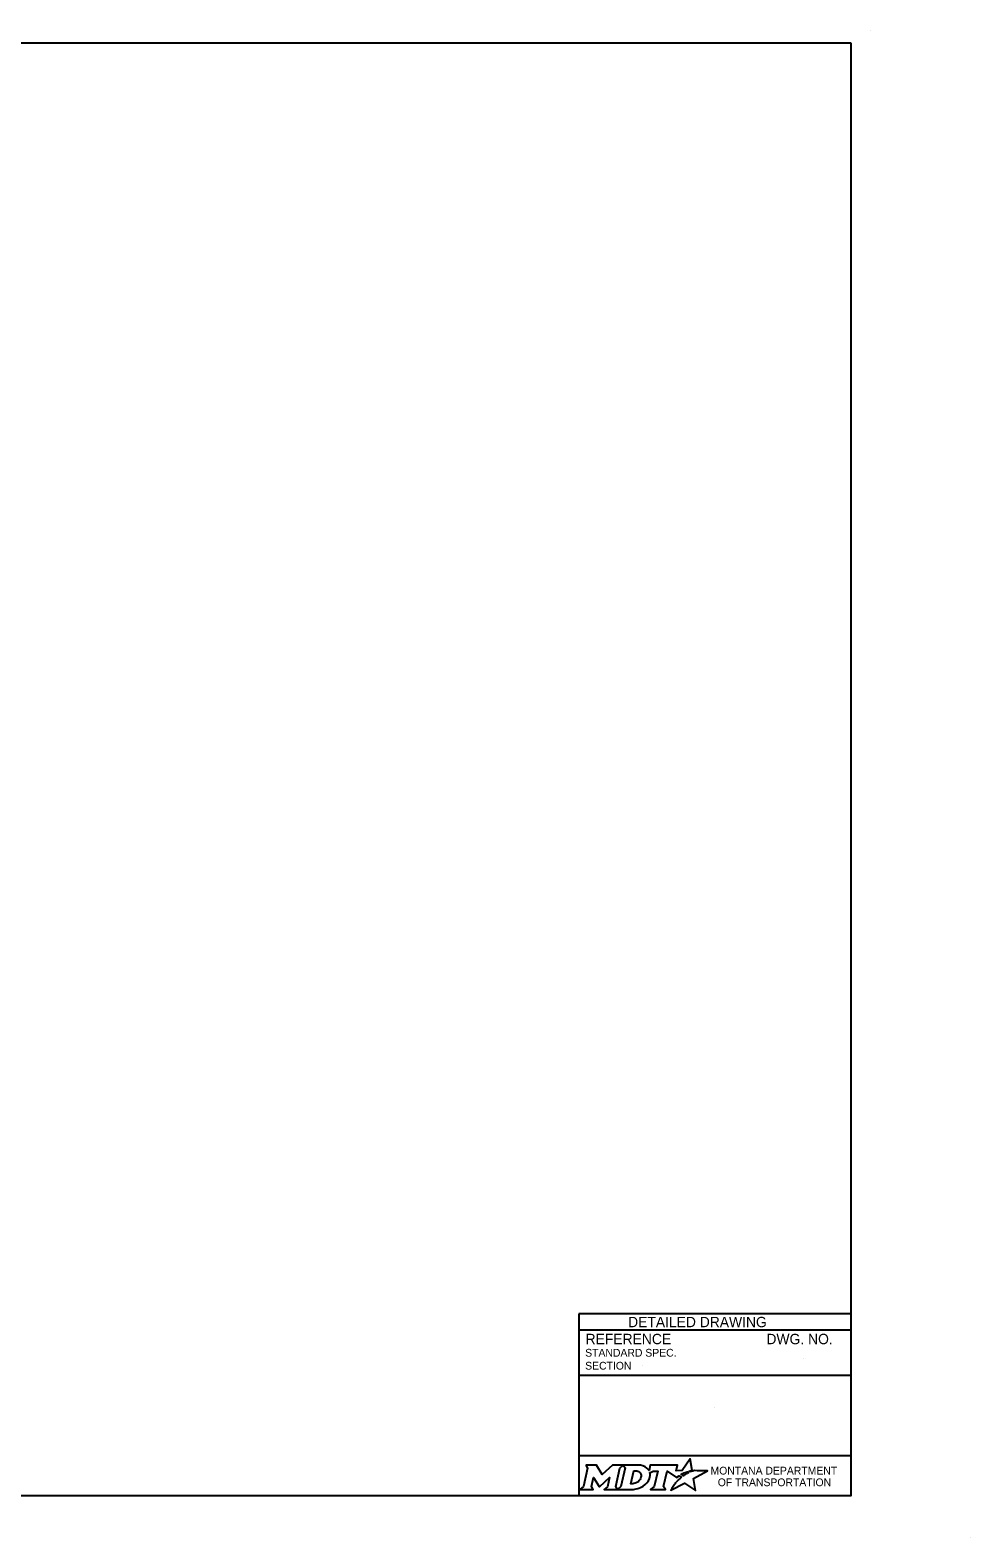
# Model space of a CAD drawing. Extents: x 49991.4 to 50021, y 49987.6 to 50011.4.
# Drawn here: x 50002.29 to 50009.54, y 49999.74 to 50011.36 of the extents above; entities that cross this region are included whole.
import ezdxf

# ---------------------------------------------------------------- set-up
doc = ezdxf.new("R2010")
doc.units = 0
doc.layers.add('Level 1', color=7, linetype='Continuous')
doc.layers.add('Level 2', color=7, linetype='Continuous')

msp = doc.modelspace()

# ---------------------------------------------------------------- linework, layer by layer
at = {"layer": 'Level 1'}
for p, q in [((50008.765, 50011.363), (50008.765, 50011.363)), ((50009.537, 49999.736), (50009.537, 49999.736))]:
    msp.add_line(p, q, dxfattribs=at)
msp.add_lwpolyline([(50008.615, 50011.263), (50000.336, 50011.263), (50000.336, 50000.062), (50008.615, 50000.062)], close=True, dxfattribs=at)
at = {"layer": 'Level 2'}
for p, q in [((50008.615, 50001.462), (50006.515, 50001.462)), ((50006.515, 50001.462), (50006.515, 50000.062)), ((50008.615, 50001.337), (50006.515, 50001.337)), ((50007.009, 50001.063), (50007.009, 50001.063)), ((50008.251, 50001.122), (50008.251, 50001.122)), ((50008.615, 50000.987), (50006.515, 50000.987)), ((50007.565, 50000.738), (50007.565, 50000.738)), ((50008.615, 50000.369), (50006.515, 50000.369))]:
    msp.add_line(p, q, dxfattribs=at)
for points in [[(50007.377, 50000.245), (50007.367, 50000.25), (50007.378, 50000.253), (50007.39, 50000.255), (50007.373, 50000.345), (50007.313, 50000.254), (50007.266, 50000.253), (50007.276, 50000.297), (50007.067, 50000.297), (50007.057, 50000.255), (50007.051, 50000.263)], [(50006.57, 50000.297), (50006.584, 50000.274), (50006.551, 50000.131), (50006.525, 50000.108), (50006.627, 50000.108), (50006.613, 50000.131), (50006.629, 50000.201), (50006.673, 50000.132), (50006.678, 50000.132), (50006.753, 50000.202), (50006.737, 50000.13), (50006.712, 50000.108), (50006.814, 50000.108), (50006.8, 50000.132), (50006.833, 50000.274)], [(50006.833, 50000.274), (50006.859, 50000.297), (50006.776, 50000.297), (50006.697, 50000.224), (50006.652, 50000.297), (50006.57, 50000.297)], [(50006.972, 50000.297), (50006.859, 50000.297), (50006.873, 50000.275), (50006.839, 50000.131), (50006.814, 50000.108), (50006.925, 50000.108)], [(50006.996, 50000.211), (50006.995, 50000.203), (50006.992, 50000.193), (50006.988, 50000.185), (50006.982, 50000.178), (50006.976, 50000.171), (50006.968, 50000.164), (50006.959, 50000.16), (50006.95, 50000.156), (50006.941, 50000.154), (50006.932, 50000.153), (50006.916, 50000.153), (50006.94, 50000.253), (50006.956, 50000.253), (50006.963, 50000.252), (50006.971, 50000.25), (50006.977, 50000.247), (50006.983, 50000.243), (50006.988, 50000.238), (50006.992, 50000.232), (50006.995, 50000.226), (50006.996, 50000.218), (50006.996, 50000.215), (50006.996, 50000.211)], [(50007.064, 50000.238), (50007.088, 50000.251), (50007.125, 50000.251), (50007.097, 50000.131), (50007.069, 50000.108), (50007.185, 50000.108), (50007.168, 50000.131), (50007.196, 50000.251), (50007.268, 50000.2), (50007.289, 50000.215), (50007.309, 50000.204)], [(50007.253, 50000.148), (50007.237, 50000.124), (50007.233, 50000.116), (50007.227, 50000.107), (50007.225, 50000.103), (50007.33, 50000.156), (50007.414, 50000.101), (50007.401, 50000.194), (50007.508, 50000.252), (50007.458, 50000.253), (50007.428, 50000.253), (50007.407, 50000.254), (50007.401, 50000.252), (50007.396, 50000.251), (50007.387, 50000.249), (50007.377, 50000.245)], [(50007.327, 50000.217), (50007.324, 50000.215), (50007.306, 50000.225), (50007.316, 50000.231), (50007.32, 50000.233), (50007.329, 50000.237), (50007.335, 50000.239), (50007.343, 50000.243), (50007.35, 50000.245), (50007.362, 50000.238), (50007.358, 50000.236), (50007.353, 50000.233), (50007.349, 50000.231), (50007.344, 50000.228), (50007.342, 50000.227), (50007.339, 50000.225), (50007.337, 50000.224), (50007.334, 50000.222), (50007.332, 50000.221), (50007.329, 50000.219), (50007.327, 50000.217)], [(50006.97, 50000.116), (50006.979, 50000.118), (50006.992, 50000.124), (50007.012, 50000.135)], [(50007.267, 50000.164), (50007.267, 50000.164)]]:
    msp.add_lwpolyline(points, dxfattribs=at)
for centre, radius, start, end in [((50006.995, 50000.219), 0.0709, 339.5329, 15.8582), ((50006.951, 50000.236), 0.118, 300.9103, 339.1383)]:
    msp.add_arc(centre, radius, start, end, dxfattribs=at)
for centre, major_axis, ratio, start_param, end_param in [((50006.97, 50000.25), (0.0834, -0.0037), 0.568097, 0.61298, 1.570796), ((50007.026, 50000.257), (0.0361, -0.0295), 0.469099, 1.225588, 1.570796), ((50006.925, 50000.257), (0, 0.148), 0.987302, 3.139398, 3.456847), ((50007.26, 50000.156), (-0.00694, -0.00806), 0.008222, 0, 3.137361), ((50007.276, 50000.174), (-0.0098, -0.0102), 0.016458, 3.141593, 6.279097), ((50007.297, 50000.194), (-0.0112, -0.0097), 0.021651, 3.157348, 6.283185)]:
    msp.add_ellipse(centre, major_axis=major_axis, ratio=ratio, start_param=start_param, end_param=end_param, dxfattribs=at)

# ---------------------------------------------------------------- texts
for s, height, p in [('DETAILED DRAWING', 0.0799, (50006.896, 50001.36)), ('REFERENCE', 0.08, (50006.568, 50001.229)), ('DWG. NO.', 0.08, (50007.962, 50001.229)), ('STANDARD SPEC.', 0.06, (50006.565, 50001.133)), ('SECTION', 0.06, (50006.565, 50001.033)), ('MONTANA DEPARTMENT', 0.06, (50007.531, 50000.224)), ('OF TRANSPORTATION', 0.06, (50007.587, 50000.134))]:
    msp.add_text(s, height=height, dxfattribs=at).set_placement(p)

doc.saveas('drawing.dxf')
